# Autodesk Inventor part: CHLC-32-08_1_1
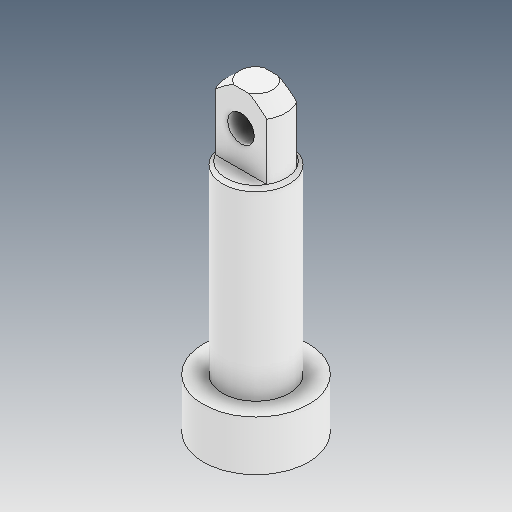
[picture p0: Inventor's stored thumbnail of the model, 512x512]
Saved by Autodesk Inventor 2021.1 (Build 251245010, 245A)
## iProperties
Created: 2021-05
Part Number: CHLC-32-08_1_1
Material: Ogólny
Document SubType Name: Modeling
Designer: user
Density: 1 g/cm^3
Appearance: Domyślna
Author: user
Revision Number: ÈÎºÎ
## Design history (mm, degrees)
feature "µ¹½Ç1"
node "Bryła1"
